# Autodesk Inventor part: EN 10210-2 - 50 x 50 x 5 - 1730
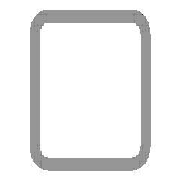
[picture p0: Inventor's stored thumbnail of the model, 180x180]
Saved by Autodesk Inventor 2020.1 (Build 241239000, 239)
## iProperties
IsCustomPart: 1
_CCFamilyMember: 16
_CCFamilyDisplayName: DIN EN 10210-2 (USAS B17.1 quadratisch) - Rohrleitung — In Klammern angegebene Größen wurden aufgehoben
_FrameMemberDoc: Frame Member File
_Version: 15.0.0
_GetPNFromCC: 1
Created: 2019-10
Part Number: EN 10210-2 - 50 x 50 x 5 - 1730
Material: Stahl, weich
Description: Rohrleitung
Document SubType Name: Modeling
Standard: DIN
Designer: lutzd
Standard Revision: 2006-07
Standards Organization: DIN
Language: de-DE
Size Designation: 50 x 50 x 5
Categories: <MemberInstance><Categories><Category DisplayName="Profile" InternalName="089c4875-fa83-4c05-b084-43b9cc11f5ed" Mnemonic="GRDR"><CategoryParameter DisplayName="
Stock Number: 50 x 50 x 5
Mass: 11841.8 g
Surface Area: 5878.4 cm^2
Volume: 1508.51 cm^3
Density: 7.85 g/cm^3
Appearance: Halbpoliert
G_L: 1730,000 mm
G_W: 50,000 mm
G_H: 50,000 mm
Dimensions: 50x50x1730 mm
Mass: 11,842 kg
DocNumber: ADSK-014090
Folder: .
+86A5FF3D-6B22-492C-8AAD-E2C3626C2CCD+SCHNITTDETAIL1: Schnittwinkel 90,00 grd
+B5F1D87C-73D7-4BE2-BFC7-FE1603E867A4+SCHNITTDETAIL2: Schnittwinkel 90,00 grd
Title: Profil-Bauteil
Author: lutzd
Revision Number: -
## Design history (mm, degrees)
node "Startebene"
node "Endebene"
sketch "Skizze"
  geometry: L1 (-25, -17.5)-(-25, 17.5); L2 (-17.5, 25)-(17.5, 25); L3 (25, 17.5)-(25, -17.5); L4 (17.5, -25)-(-17.5, -25); L5 (-15, 20)-(15, 20); L6 (20, 15)-(20, -15); L7 (15, -20)-(-15, -20); L8 (-20, -15)-(-20, 15); L9 (0, 37.175)-(0, -37.175) reference; L10 (-37.175, 0)-(37.175, 0) reference; A1 r 7.5 centre (-17.5, -17.5) between (-25, -17.5) and (-17.5, -25); A2 r 7.5 centre (-17.5, 17.5) between (-17.5, 25) and (-25, 17.5); A3 r 7.5 centre (17.5, 17.5) between (25, 17.5) and (17.5, 25); A4 r 7.5 centre (17.5, -17.5) between (17.5, -25) and (25, -17.5); A5 r 5 centre (-15, -15) between (-20, -15) and (-15, -20); A6 r 5 centre (-15, 15) between (-15, 20) and (-20, 15); A7 r 5 centre (15, 15) between (20, 15) and (15, 20); A8 r 5 centre (15, -15) between (15, -20) and (20, -15)
  constraints: 16 end point, 16 point on circle, 16 tangent, 8 centre point, 6 equal radius, 4 parallel, 2 perpendicular, 2 other
  dimensions: "d7" = 7.5 radius of A1 (= G_IR); "d10" = 50 distance between parallel lines of L2 L4 (= G_H); "d11" = 50 distance between parallel lines of L1 L3 (= G_W); "d12" = 5 distance between parallel lines of L3 L6 (= G_T); "d15" = 25 distance between parallel lines of L2 L10 (= 0.5 x d10); "d16" = 25 distance between parallel lines of L9 L3 (= 0.5 x d11); "d19" = 5 radius of A5 (= G_T); "d20" = 5 distance between parallel lines of L4 L7 (= G_T)
extrude "Körper" new body sketch "Skizze" stored distance "d3" = 1730 (= G_L); taper "d4" = 0 deg
node "Driven Length"
  sketch "Sketch3"
    geometry: L1 (0, 0)-(10, 0) reference
    constraints: 2 end point, 1 horizontal
  workplane "Work Plane3"
  sketch "Sketch4"
    geometry: L1 (-2, 50)-(12, 50) reference; L2 (-2, 1780)-(12, 1780) reference
    dimensions: "d18" = 1730 distance between parallel lines of L1 L2 (derived)
workplane "Arbeitsebene4"
feature "Trennen1"
workplane "Arbeitsebene5"
feature "Trennen2"
sketch "Skizze5"
  geometry: L1 (-35, 1730)-(0, 1730) reference; L2 (-17.5, 1730)-(-17.5, 1305); 3 further points
  constraints: 2 end point, 1 coincident, 1 midpoint, 1 point on line, 1 vertical
  dimensions: "d21" = 95 distance of point (-17.5, 1305) point (-17.5, 1400); "d30" = 330 distance from line of L1 point (-17.5, 1400)
hole "Bohrung1" sketch "Skizze5" at (-17.5, 1305), (-17.5, 1400) diameter "d23" = 6.647; stored, may be unused: countersink angle "d27" = 90 deg, drill point angle "d29" = 0 deg; dims "d24" = 16, "d25" = 4, "d26" = 2, "d28" = 8
sketch "Skizze6"
  geometry: L1 (0, -35)-(0, 0) reference; L2 (0, -17.5)-(1429.5, -17.5); 5 further points
  constraints: 3 point on line, 2 end point, 1 coincident, 1 horizontal, 1 midpoint
  dimensions: "d31" = 63.5 distance of point (1366, -17.5) point (1429.5, -17.5); "d32" = 63.5 distance of point (1137.5, -17.5) point (1201, -17.5) (= d31); "d33" = 165 distance of point (1366, -17.5) point (1201, -17.5); "d34" = 1137.5 distance from line of L1 point (1137.5, -17.5)
hole "Bohrung2" sketch "Skizze6" at (1429.5, -17.5), (1366, -17.5), (1201, -17.5), (1137.5, -17.5) diameter "d35" = 6.647; stored, may be unused: countersink angle "d39" = 90 deg, drill point angle "d41" = 118 deg; dims "d36" = 16, "d37" = 4, "d38" = 2, "d40" = 8
sketch "Skizze7"
  geometry: L1 (1116, 19.731)-(792, 19.731); L2 (1730, 35)-(1730, 0) reference; 3 further points
  constraints: 2 end point, 1 coincident, 1 horizontal, 1 midpoint
  dimensions: "d42" = 162 distance of point (954, 19.731) L1.end; "d43" = 162 distance of point (954, 19.731) L1.start (derived); "d44" = 614 distance from line of L2 L1.start
hole "Bohrung3" sketch "Skizze7" at (1116, 19.731), (954, 19.731), (792, 19.731) diameter "d45" = 6.647; stored, may be unused: countersink angle "d49" = 90 deg, drill point angle "d51" = 118 deg; dims "d46" = 16, "d47" = 4, "d48" = 2, "d50" = 22.2
sketch "Skizze8"
  geometry: L1 (35, 1730)-(0, 1730) reference; L2 (17.5, 1730)-(17.5, 1131); 4 further points
  constraints: 2 end point, 2 point on line, 1 coincident, 1 midpoint, 1 vertical
  dimensions: "d52" = 115 distance of point (17.5, 1246) point (17.5, 1131); "d53" = 115 distance of point (17.5, 1361) point (17.5, 1246) (= d52); "d54" = 369 distance from line of L1 point (17.5, 1361)
hole "Bohrung4" sketch "Skizze8" at (17.5, 1361), (17.5, 1246), (17.5, 1131) diameter "d55" = 6.647; stored, may be unused: countersink angle "d59" = 90 deg, drill point angle "d61" = 118 deg; dims "d56" = 16, "d57" = 4, "d58" = 2, "d60" = 8
body "Solid1"
other parameters: "G_W" = 50 [user parameter; used in 1 equation term], "G_H" = 50 [user parameter; used in 1 equation term], "G_T" = 5 [user parameter; used in 3 equation terms], "G_IR" = 7.5 [user parameter; used in 1 equation term], "G_L" = 1730 (= d18) [user parameter; used in 1 equation term], "d17" = 90 deg
